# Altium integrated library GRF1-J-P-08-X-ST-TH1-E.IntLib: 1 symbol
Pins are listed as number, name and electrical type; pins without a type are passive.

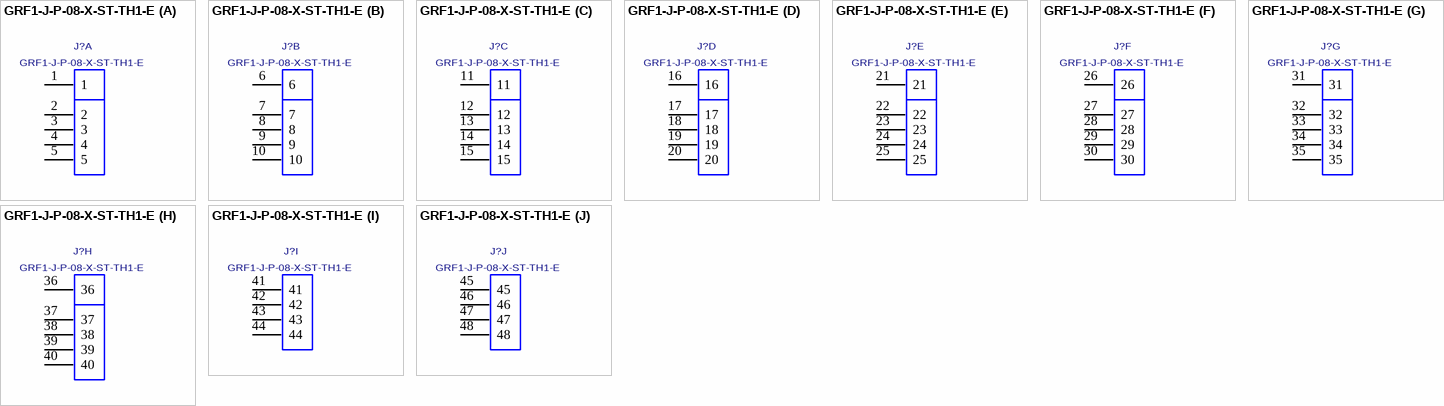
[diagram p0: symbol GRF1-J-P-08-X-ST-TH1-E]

## GRF1-J-P-08-X-ST-TH1-E
designator J?
GANGED RF JACK CONNECTOR.; MANUFACTURER: SAMTEC
footprint GRF1-J-P-08-X-ST-TH1-E
part A pins: 1, 2, 3, 4, 5
part B pins: 6, 7, 8, 9, 10
part C pins: 11, 12, 13, 14, 15
part D pins: 16, 17, 18, 19, 20
part E pins: 21, 22, 23, 24, 25
part F pins: 26, 27, 28, 29, 30
part G pins: 31, 32, 33, 34, 35
part H pins: 36, 37, 38, 39, 40
part I pins: 41, 42, 43, 44
part J pins: 45, 46, 47, 48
